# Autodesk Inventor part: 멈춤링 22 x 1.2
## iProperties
IsCustomPart: 0
Created: 2009-02
Part Number: 멈춤링 22 x 1.2
Material: Steel, Mild
Description: 리테이닝 링(C형)
Document SubType Name: Modeling
Standard: KS B 1336
Designer: SeoGD™
Standards Organization: KS
Language: ko-KR
Size Designation: 22 x 1.2
Categories: <MemberInstance><Categories><Category DisplayName="샤프트 부품" InternalName="7f7aeb1f-a693-4053-b835-cee3144e0d98" Mnemonic="SHFT"><Category DisplayName="써클립" Inter
Density: 1 g/cm^3
Author: SeoGD™
